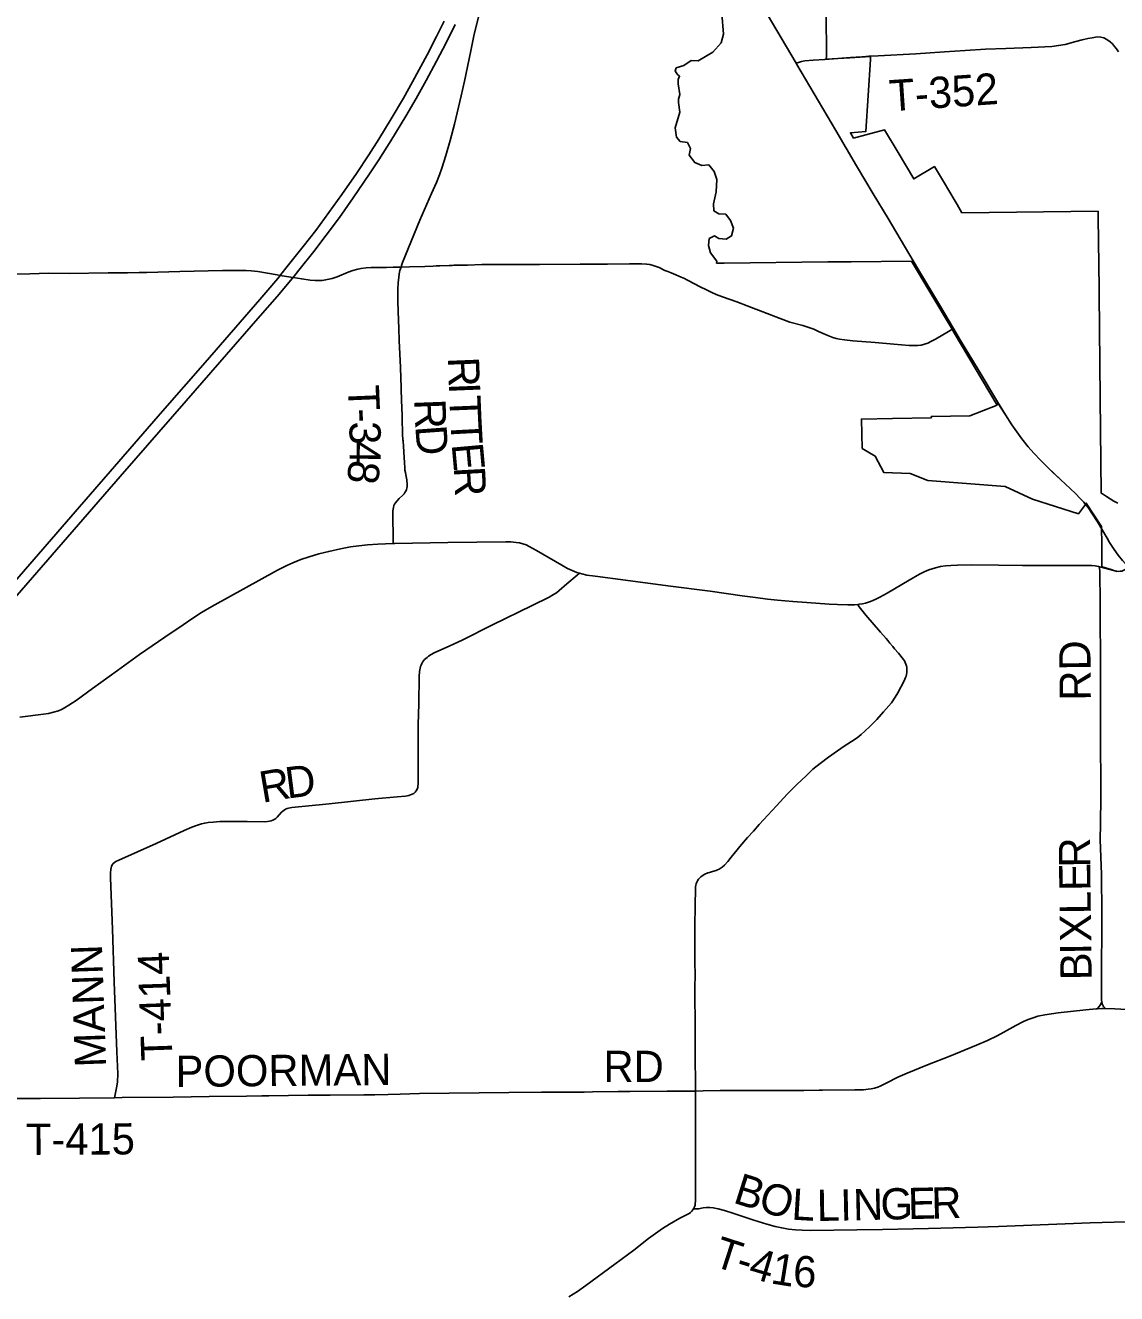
# Model space of a CAD drawing. Extents: x 40529 to 41139, y 15164 to 15584.
# Drawn here: x 40618.2 to 40677.8, y 15358.4 to 15427.7 of the extents above; entities that cross this region are included whole.
import ezdxf

# ---------------------------------------------------------------- set-up
doc = ezdxf.new("R2010")
doc.units = 0
for name, color, linetype in [('GM_X_Corporation', 7, 'Continuous'), ('GM_X_County_Road', 7, 'Continuous'), ('GM_X_Interstate_Route', 7, 'Continuous'), ('GM_X_State_Route', 7, 'Continuous'), ('GM_X_Township_Road', 7, 'Continuous'), ('GM_X_Township_Road_Text', 7, 'Continuous'), ('SH_Data', 7, 'Continuous')]:
    doc.layers.add(name, color=color, linetype=linetype)

msp = doc.modelspace()

# ---------------------------------------------------------------- linework, layer by layer
at = {"layer": 'GM_X_Corporation'}
for points in [[(40677.842, 15397.878), (40677.786, 15397.892), (40677.731, 15397.91), (40677.466, 15398.003), (40677.348, 15398.04), (40677.229, 15398.074), (40677.034, 15398.122), (40677.02, 15398.125), (40677.019, 15398.303), (40677.014, 15399.659), (40677.01, 15399.989), (40677.007, 15400.331), (40676.172, 15401.606), (40676.068, 15401.464), (40675.744, 15401.025), (40673.227, 15401.82), (40671.732, 15402.507), (40667.514, 15402.848), (40666.546, 15403.228), (40665.117, 15403.274), (40664.639, 15404.173), (40663.92, 15404.595), (40663.889, 15406.199), (40665.576, 15406.231), (40667.706, 15406.272), (40667.703, 15406.337), (40669.811, 15406.384), (40671.298, 15406.968), (40668.954, 15410.907), (40668.78, 15411.201), (40666.62, 15414.831), (40663.332, 15414.797), (40662.05, 15414.784), (40656.379, 15414.726), (40655.97, 15414.724), (40655.987, 15414.836), (40655.636, 15415.287), (40655.531, 15415.686), (40655.573, 15416.064), (40655.866, 15416.204), (40656.098, 15416.064), (40656.496, 15416.022), (40656.79, 15416.211), (40656.895, 15416.631), (40656.727, 15417.051), (40656.475, 15417.387), (40656.098, 15417.408), (40655.825, 15417.576), (40655.804, 15417.954), (40655.95, 15418.619), (40655.992, 15419.29), (40655.835, 15419.727), (40655.552, 15420.088), (40655.174, 15420.046), (40654.775, 15420.214), (40654.481, 15420.613), (40654.544, 15420.991), (40654.376, 15421.306), (40653.978, 15421.369), (40653.789, 15421.6), (40653.705, 15422.104), (40653.957, 15422.964), (40653.889, 15423.49), (40653.889, 15423.684), (40653.957, 15423.93), (40653.873, 15424.518), (40653.868, 15424.753), (40653.952, 15424.926), (40653.821, 15425.052), (40653.71, 15425.225), (40653.768, 15425.383), (40654.187, 15425.526), (40654.587, 15425.792), (40654.964, 15425.778), (40655.761, 15426.24), (40656.223, 15426.764), (40656.349, 15427.226), (40656.257, 15428.352)], [(40661.957, 15428.401), (40661.973, 15426.025), (40661.967, 15425.858), (40663.255, 15425.937), (40664.382, 15426.006), (40664.375, 15425.838), (40664.134, 15421.913), (40663.283, 15421.844), (40663.458, 15421.55), (40664.122, 15421.725), (40665.151, 15421.997), (40665.886, 15420.762), (40666.742, 15419.322), (40667.877, 15419.997), (40668.53, 15418.899), (40668.548, 15418.868), (40669.116, 15417.914), (40669.376, 15417.476), (40676.819, 15417.553), (40676.828, 15416.772), (40676.832, 15416.357), (40676.84, 15415.647), (40676.841, 15415.609), (40676.848, 15414.936), (40676.93, 15407.341), (40676.987, 15402.158), (40677.064, 15402.109), (40677.269, 15401.977), (40677.475, 15401.848), (40677.684, 15401.723), (40677.895, 15401.602)]]:
    msp.add_lwpolyline(points, dxfattribs=at)
at = {"layer": 'GM_X_County_Road'}
for points in [[(40617.414, 15414.121), (40618.462, 15414.136), (40619.479, 15414.163), (40620.606, 15414.16), (40622.738, 15414.187), (40623.174, 15414.195), (40623.537, 15414.191), (40623.798, 15414.191), (40624.425, 15414.199), (40624.846, 15414.21), (40626.646, 15414.255), (40628.974, 15414.311), (40629.81, 15414.325), (40630.273, 15414.318), (40630.55, 15414.299), (40630.918, 15414.254), (40631.967, 15414.078), (40632.133, 15414.051), (40632.712, 15413.957), (40632.836, 15413.936), (40633.306, 15413.857), (40633.768, 15413.791), (40634.049, 15413.767), (40634.237, 15413.766), (40634.424, 15413.779), (40634.611, 15413.804), (40634.796, 15413.84), (40634.977, 15413.888), (40635.243, 15413.979), (40635.839, 15414.226), (40636.099, 15414.321), (40636.365, 15414.394), (40636.546, 15414.427), (40636.821, 15414.458), (40637.099, 15414.474), (40637.937, 15414.484), (40638.298, 15414.5), (40638.733, 15414.503)], [(40638.733, 15414.503), (40639.196, 15414.515), (40640.03, 15414.53), (40640.486, 15414.55), (40640.659, 15414.564), (40640.857, 15414.569), (40641.371, 15414.589), (40641.519, 15414.596), (40641.612, 15414.601), (40641.673, 15414.602), (40641.728, 15414.603), (40641.822, 15414.609), (40641.9, 15414.612), (40642.356, 15414.612), (40643.145, 15414.645), (40643.328, 15414.645), (40643.4, 15414.646), (40643.458, 15414.646), (40643.671, 15414.649), (40643.744, 15414.65), (40644.282, 15414.647), (40645.261, 15414.64), (40646.301, 15414.647), (40648.519, 15414.664), (40650.01, 15414.666), (40651.222, 15414.685), (40651.873, 15414.685), (40652.151, 15414.672), (40652.331, 15414.64), (40652.502, 15414.597), (40652.677, 15414.538), (40652.837, 15414.472), (40653.145, 15414.32), (40653.301, 15414.254), (40653.488, 15414.184), (40653.617, 15414.141), (40654.038, 15413.958), (40654.225, 15413.872), (40654.342, 15413.809), (40654.424, 15413.763), (40655.074, 15413.42), (40655.425, 15413.252), (40655.678, 15413.135), (40655.944, 15413.007), (40656.287, 15412.87), (40657.07, 15412.597), (40657.635, 15412.395), (40658.734, 15411.97), (40659.451, 15411.697), (40659.977, 15411.498), (40660.683, 15411.307), (40661.118, 15411.172), (40661.291, 15411.105), (40661.544, 15410.991), (40662.053, 15410.757), (40662.317, 15410.658), (40662.498, 15410.607), (40662.682, 15410.567), (40662.96, 15410.524), (40663.424, 15410.476), (40664.632, 15410.379), (40665.653, 15410.294), (40666.49, 15410.226), (40666.771, 15410.216), (40666.96, 15410.222), (40667.147, 15410.245), (40667.331, 15410.289), (40667.509, 15410.352), (40667.68, 15410.431), (40667.927, 15410.565), (40668.649, 15410.993), (40668.915, 15411.151)], [(40617.91, 15389.921), (40619.206, 15390.077), (40619.48, 15390.121), (40619.751, 15390.183), (40620.015, 15390.266), (40620.185, 15390.337), (40620.351, 15390.418), (40620.59, 15390.56), (40620.976, 15390.818), (40621.883, 15391.472), (40623.24, 15392.46), (40624.452, 15393.328), (40625.827, 15394.288), (40626.824, 15394.964), (40627.364, 15395.331), (40627.829, 15395.633), (40628.404, 15395.957), (40631.989, 15397.949), (40632.489, 15398.199), (40632.83, 15398.352), (40633.264, 15398.52), (40633.705, 15398.671), (40634.243, 15398.828), (40634.785, 15398.967), (40635.423, 15399.109), (40635.974, 15399.213), (40636.436, 15399.282), (40636.9, 15399.33), (40637.459, 15399.368), (40638.3, 15399.401)], [(40638.3, 15399.401), (40638.392, 15399.405), (40641.282, 15399.451), (40644.452, 15399.489), (40644.733, 15399.484), (40645.014, 15399.464), (40645.201, 15399.436), (40645.385, 15399.391), (40645.562, 15399.326), (40645.733, 15399.245), (40646.141, 15399.018), (40647.509, 15398.219), (40647.835, 15398.042), (40648.087, 15397.924), (40648.345, 15397.821), (40648.48, 15397.78)], [(40648.48, 15397.78), (40648.61, 15397.74), (40648.881, 15397.68), (40649.34, 15397.611), (40651.005, 15397.398), (40653.316, 15397.092), (40655.627, 15396.79), (40657.379, 15396.547), (40658.105, 15396.454), (40658.747, 15396.366), (40659.297, 15396.302), (40660.13, 15396.228), (40660.896, 15396.187), (40662.117, 15396.085), (40662.581, 15396.06), (40663.14, 15396.05), (40663.504, 15396.059), (40663.693, 15396.074)], [(40663.693, 15396.074), (40663.757, 15396.079), (40663.938, 15396.104), (40664.117, 15396.146), (40664.38, 15396.232), (40664.636, 15396.34), (40664.886, 15396.462), (40665.292, 15396.688), (40666.497, 15397.399), (40667.066, 15397.721), (40667.317, 15397.847), (40667.575, 15397.959), (40667.752, 15398.024), (40667.932, 15398.078), (40668.207, 15398.138), (40668.485, 15398.18), (40668.765, 15398.208), (40669.139, 15398.225), (40669.886, 15398.228), (40671.377, 15398.223), (40672.682, 15398.206), (40675.293, 15398.202), (40675.754, 15398.203), (40676.209, 15398.204), (40676.477, 15398.197), (40676.661, 15398.178), (40676.846, 15398.143), (40676.892, 15398.131)], [(40676.892, 15398.131), (40677.118, 15398.073), (40677.657, 15397.919), (40677.836, 15397.887), (40677.926, 15397.88), (40678.016, 15397.882), (40678.104, 15397.895), (40678.19, 15397.921), (40678.261, 15397.967), (40678.309, 15398.015), (40678.446, 15398.152)]]:
    msp.add_lwpolyline(points, dxfattribs=at)
at = {"layer": 'GM_X_Interstate_Route'}
for points in [[(40615.607, 15395.019), (40620.689, 15400.855), (40625.703, 15406.623), (40628.029, 15409.295), (40631.027, 15412.741), (40631.993, 15413.878), (40632.133, 15414.051), (40632.169, 15414.095), (40632.517, 15414.532), (40633.391, 15415.624), (40634.075, 15416.51), (40634.796, 15417.485), (40635.501, 15418.471), (40636.294, 15419.623), (40636.966, 15420.632), (40637.517, 15421.497), (40638.196, 15422.612), (40638.859, 15423.736), (40639.363, 15424.63), (40640.16, 15426.107), (40640.677, 15427.099), (40641.09, 15427.934)], [(40617.395, 15396.161), (40623.387, 15403.059), (40627.003, 15407.204), (40631.039, 15411.848), (40631.96, 15412.901), (40632.803, 15413.896), (40632.836, 15413.936), (40633.158, 15414.328), (40633.967, 15415.351), (40634.645, 15416.241), (40635.363, 15417.218), (40636.117, 15418.283), (40637.013, 15419.59), (40637.524, 15420.369), (40638.169, 15421.395), (40638.99, 15422.75), (40639.554, 15423.715), (40640.101, 15424.69), (40640.677, 15425.756), (40641.19, 15426.749), (40641.685, 15427.752)]]:
    msp.add_lwpolyline(points, dxfattribs=at)
at = {"layer": 'GM_X_State_Route'}
for points in [[(40656.221, 15439.212), (40656.386, 15438.467), (40656.534, 15437.735), (40656.695, 15436.815), (40656.88, 15435.617), (40657.181, 15433.493), (40657.36, 15432.294), (40657.515, 15431.186), (40657.608, 15430.635), (40657.676, 15430.366), (40657.764, 15430.103), (40657.872, 15429.848), (40657.996, 15429.6), (40658.224, 15429.194), (40658.734, 15428.328), (40660.317, 15425.637), (40660.353, 15425.577), (40662.489, 15421.965), (40663.621, 15420.034), (40664.526, 15418.511), (40665.341, 15417.151), (40666.718, 15414.843)], [(40666.718, 15414.843), (40667.061, 15414.268), (40668.204, 15412.344), (40668.915, 15411.151), (40669.302, 15410.501), (40670.263, 15408.902), (40671.311, 15407.139), (40671.364, 15407.053)], [(40671.364, 15407.053), (40671.75, 15406.423), (40672.104, 15405.877), (40672.37, 15405.495), (40672.65, 15405.123), (40673.001, 15404.689), (40673.306, 15404.338), (40673.687, 15403.929), (40674.083, 15403.534), (40674.323, 15403.307)], [(40674.323, 15403.307), (40674.76, 15402.894), (40675.58, 15402.132), (40675.844, 15401.866), (40676.033, 15401.658), (40676.056, 15401.628)], [(40676.056, 15401.628), (40676.265, 15401.364), (40676.477, 15401.055), (40676.775, 15400.581), (40677.306, 15399.697)], [(40677.306, 15399.697), (40677.447, 15399.461), (40677.701, 15399.071), (40677.917, 15398.769), (40678.148, 15398.478), (40678.332, 15398.269), (40678.446, 15398.152)]]:
    msp.add_lwpolyline(points, dxfattribs=at)
at = {"layer": 'GM_X_Township_Road'}
for points in [[(40638.733, 15414.503), (40638.76, 15414.585), (40638.822, 15414.756), (40639.76, 15417.075), (40640.392, 15418.527), (40640.663, 15419.123), (40640.837, 15419.552), (40640.959, 15419.901), (40641.183, 15420.608), (40641.415, 15421.412), (40641.651, 15422.312), (40642.021, 15423.852), (40642.207, 15424.669), (40642.549, 15426.31), (40642.734, 15427.224), (40642.885, 15427.86), (40642.99, 15428.241), (40642.998, 15428.268)], [(40664.293, 15426.02), (40664.806, 15426.054), (40666.853, 15426.158), (40668.429, 15426.263), (40669.554, 15426.337), (40670.658, 15426.41), (40671.775, 15426.454), (40673.167, 15426.501), (40674.294, 15426.55), (40675.015, 15426.668), (40675.592, 15426.831), (40675.952, 15426.915), (40676.248, 15426.989), (40676.499, 15427.032), (40676.766, 15427.082), (40676.963, 15427.072), (40677.131, 15427.033), (40677.299, 15426.939), (40677.476, 15426.811), (40677.6, 15426.702), (40677.713, 15426.559), (40677.817, 15426.421), (40677.93, 15426.263)], [(40661.884, 15425.854), (40663.291, 15425.948), (40663.901, 15425.994), (40663.97, 15425.999), (40664.293, 15426.02)], [(40660.317, 15425.637), (40660.511, 15425.704), (40660.603, 15425.736), (40660.789, 15425.767), (40661.252, 15425.812), (40661.884, 15425.854)], [(40638.558, 15412.636), (40638.553, 15412.823), (40638.559, 15413.289), (40638.583, 15413.662), (40638.611, 15413.941), (40638.637, 15414.128), (40638.676, 15414.312), (40638.733, 15414.503)], [(40638.84, 15405.074), (40638.82, 15405.38), (40638.81, 15405.667), (40638.8, 15405.95), (40638.789, 15406.32), (40638.778, 15406.878), (40638.766, 15407.156), (40638.748, 15407.898), (40638.695, 15409.009), (40638.627, 15410.497), (40638.616, 15411.143), (40638.573, 15412.074), (40638.558, 15412.636)], [(40638.3, 15399.401), (40638.298, 15399.597), (40638.282, 15400.996), (40638.281, 15401.178), (40638.295, 15401.286), (40638.318, 15401.377), (40638.348, 15401.471), (40638.382, 15401.545), (40638.433, 15401.629), (40638.504, 15401.714), (40638.632, 15401.855), (40638.836, 15402.044), (40638.896, 15402.113), (40638.948, 15402.187), (40638.994, 15402.264), (40639.029, 15402.346), (40639.054, 15402.432), (40639.069, 15402.521), (40639.074, 15402.608), (40639.054, 15402.884), (40638.999, 15403.153), (40638.968, 15403.281), (40638.948, 15403.412), (40638.932, 15403.547), (40638.915, 15403.813), (40638.844, 15405.013), (40638.84, 15405.074)], [(40623.087, 15369.122), (40623.215, 15369.754), (40623.247, 15369.997), (40623.253, 15370.425), (40623.21, 15371.635), (40623.061, 15375.45), (40622.963, 15378.335), (40622.856, 15381.127), (40622.86, 15381.406), (40622.877, 15381.589), (40622.895, 15381.677), (40622.921, 15381.761), (40622.957, 15381.84), (40623.01, 15381.91), (40623.076, 15381.97), (40623.149, 15382.021), (40623.311, 15382.109), (40624.333, 15382.556), (40625.356, 15383.009), (40626.876, 15383.716), (40627.302, 15383.902), (40627.562, 15384), (40627.827, 15384.081), (40628.006, 15384.123), (40628.188, 15384.153), (40628.464, 15384.182), (40628.835, 15384.205), (40629.3, 15384.216), (40630.324, 15384.207), (40631.256, 15384.203), (40631.445, 15384.212), (40631.54, 15384.224), (40631.633, 15384.246), (40631.724, 15384.278), (40631.81, 15384.322), (40631.889, 15384.378), (40631.96, 15384.442), (40632.209, 15384.721), (40632.274, 15384.784), (40632.343, 15384.84), (40632.42, 15384.885), (40632.503, 15384.919), (40632.589, 15384.946), (40632.769, 15384.979), (40633.14, 15385.011), (40633.51, 15385.047), (40634.808, 15385.18), (40637.308, 15385.448), (40638.514, 15385.559), (40638.98, 15385.604), (40639.167, 15385.638), (40639.258, 15385.664), (40639.347, 15385.701), (40639.43, 15385.751), (40639.504, 15385.814), (40639.565, 15385.891), (40639.612, 15385.977), (40639.643, 15386.069), (40639.658, 15386.164), (40639.667, 15386.259), (40639.669, 15387.006), (40639.668, 15388.496), (40639.677, 15389.52), (40639.71, 15390.637), (40639.732, 15392.128), (40639.744, 15392.405), (40639.772, 15392.585), (40639.795, 15392.673), (40639.825, 15392.758), (40639.862, 15392.839), (40639.908, 15392.917), (40639.96, 15392.991), (40640.018, 15393.06), (40640.083, 15393.123), (40640.153, 15393.182), (40640.226, 15393.237), (40640.382, 15393.334), (40640.546, 15393.419), (40641.393, 15393.806), (40642.066, 15394.127), (40643.736, 15394.955), (40645.9, 15396.021), (40646.82, 15396.475), (40647.066, 15396.611), (40647.225, 15396.711), (40647.375, 15396.825), (40647.798, 15397.191), (40648.358, 15397.674), (40648.48, 15397.78)], [(40677.012, 15374.369), (40677.008, 15374.454), (40677.006, 15374.535), (40677.001, 15374.727), (40676.993, 15374.982), (40677.003, 15375.377), (40677.021, 15379.167), (40676.994, 15381.308), (40676.928, 15383.236), (40676.944, 15384.078), (40676.974, 15385.563), (40676.963, 15386.484), (40676.953, 15388.303), (40676.938, 15391.195), (40676.938, 15392.93), (40676.928, 15395.48), (40676.931, 15396.506), (40676.912, 15397.53), (40676.903, 15397.809), (40676.892, 15398.131)], [(40654.821, 15369.482), (40654.819, 15370.052), (40654.808, 15371.17), (40654.804, 15371.634), (40654.799, 15372.84), (40654.789, 15375.066), (40654.796, 15375.903), (40654.792, 15376.46), (40654.789, 15377.483), (40654.788, 15378.412), (40654.801, 15379.711), (40654.812, 15380.454), (40654.825, 15380.637), (40654.839, 15380.726), (40654.861, 15380.813), (40654.893, 15380.897), (40654.933, 15380.978), (40654.981, 15381.053), (40655.038, 15381.121), (40655.103, 15381.182), (40655.176, 15381.236), (40655.334, 15381.327), (40655.497, 15381.4), (40655.581, 15381.429), (40655.758, 15381.48), (40655.941, 15381.532), (40656.029, 15381.569), (40656.111, 15381.61), (40656.269, 15381.719), (40656.399, 15381.825), (40656.585, 15382.035), (40656.775, 15382.268), (40656.929, 15382.458), (40657.091, 15382.656), (40657.245, 15382.849), (40657.668, 15383.344), (40657.981, 15383.691), (40658.305, 15384.051), (40659.242, 15385.075), (40659.823, 15385.708), (40660.357, 15386.241), (40660.859, 15386.716), (40661.238, 15387.068), (40661.626, 15387.38), (40662.08, 15387.736), (40662.581, 15388.072), (40662.95, 15388.333), (40663.351, 15388.576), (40663.657, 15388.789), (40663.874, 15388.961), (40664.079, 15389.141), (40664.344, 15389.398), (40664.729, 15389.794), (40665.096, 15390.209), (40665.52, 15390.689), (40665.728, 15390.998), (40665.871, 15391.239), (40666.212, 15391.901), (40666.29, 15392.072), (40666.322, 15392.161), (40666.348, 15392.253), (40666.365, 15392.347), (40666.374, 15392.442), (40666.373, 15392.537), (40666.364, 15392.632), (40666.346, 15392.724), (40666.319, 15392.815), (40666.282, 15392.904), (40666.237, 15392.988), (40666.186, 15393.068), (40665.911, 15393.417), (40665.701, 15393.65), (40665.603, 15393.769), (40665.44, 15393.954), (40665.322, 15394.108), (40665.244, 15394.206), (40664.931, 15394.559), (40664.124, 15395.48), (40663.826, 15395.842), (40663.77, 15395.94), (40663.693, 15396.074)], [(40677.214, 15373.991), (40677.738, 15373.977), (40678.393, 15373.934), (40680.151, 15373.779), (40681.636, 15373.717), (40682.675, 15373.651), (40683.787, 15373.568), (40684.429, 15373.513), (40684.623, 15373.506), (40684.716, 15373.503), (40684.802, 15373.506), (40684.895, 15373.52), (40684.989, 15373.554), (40685.061, 15373.603), (40685.141, 15373.662), (40685.207, 15373.724), (40685.273, 15373.785), (40685.394, 15373.922), (40685.619, 15374.218), (40686.752, 15375.814), (40687.777, 15377.281)], [(40676.791, 15373.986), (40676.862, 15374.083), (40676.945, 15374.194), (40676.972, 15374.253), (40677.012, 15374.369)], [(40677.214, 15373.991), (40677.111, 15374.112), (40677.062, 15374.211), (40677.012, 15374.369)], [(40654.821, 15369.482), (40655.236, 15369.489), (40656.169, 15369.508), (40660.742, 15369.518), (40661.581, 15369.525), (40661.766, 15369.535), (40663.532, 15369.547), (40663.993, 15369.561), (40664.254, 15369.584), (40664.42, 15369.609), (40664.595, 15369.65), (40664.774, 15369.706), (40664.939, 15369.77), (40665.267, 15369.926), (40665.88, 15370.238), (40666.378, 15370.464), (40667.501, 15370.924), (40668.715, 15371.398), (40670.181, 15371.989), (40670.773, 15372.245), (40671.293, 15372.496), (40671.673, 15372.699), (40672.33, 15373.067), (40672.746, 15373.281), (40673.004, 15373.392), (40673.265, 15373.491), (40673.532, 15373.572), (40673.899, 15373.645), (40674.635, 15373.75), (40676.154, 15373.927), (40676.717, 15373.984), (40676.791, 15373.986)], [(40676.791, 15373.986), (40677.022, 15373.992), (40677.214, 15373.991)], [(40623.087, 15369.122), (40623.501, 15369.129), (40626.292, 15369.155), (40628.247, 15369.185), (40630.298, 15369.211), (40631.137, 15369.217), (40631.511, 15369.217), (40633.655, 15369.259), (40634.86, 15369.267), (40636.707, 15369.271), (40637.302, 15369.281), (40638.022, 15369.295), (40638.685, 15369.322), (40639.736, 15369.353), (40644.63, 15369.401), (40646.402, 15369.418), (40647.8, 15369.42), (40648.731, 15369.431), (40649.197, 15369.434), (40650.591, 15369.462), (40651.241, 15369.465), (40653.28, 15369.471), (40653.995, 15369.478), (40654.821, 15369.482)], [(40654.715, 15363.05), (40654.73, 15363.078), (40654.767, 15363.167), (40654.794, 15363.259), (40654.81, 15363.353), (40654.818, 15363.446), (40654.828, 15363.819), (40654.824, 15367.538), (40654.821, 15369.482)], [(40615.981, 15368.667), (40616.025, 15368.772), (40616.084, 15368.851), (40616.155, 15368.92), (40616.234, 15368.974), (40616.327, 15369.012), (40616.419, 15369.044), (40616.513, 15369.063), (40616.702, 15369.079), (40619.033, 15369.084), (40621.174, 15369.099), (40623.087, 15369.122)], [(40647.9, 15358.236), (40648.367, 15358.541), (40648.825, 15358.863), (40650.405, 15360.02), (40651.457, 15360.793), (40652.261, 15361.425), (40652.63, 15361.707), (40653.012, 15361.97), (40653.405, 15362.217), (40653.97, 15362.541), (40654.468, 15362.8), (40654.548, 15362.853), (40654.621, 15362.916), (40654.683, 15362.993), (40654.715, 15363.05)], [(40654.715, 15363.05), (40654.836, 15363.053), (40654.999, 15363.057), (40655.151, 15363.092), (40655.24, 15363.108), (40655.422, 15363.127), (40655.604, 15363.127), (40655.786, 15363.108), (40656.056, 15363.053), (40656.413, 15362.955), (40656.855, 15362.812), (40658.004, 15362.427), (40658.718, 15362.209), (40659.17, 15362.089), (40659.536, 15362.009), (40659.905, 15361.948), (40660.277, 15361.904), (40660.65, 15361.88), (40661.118, 15361.873), (40663.636, 15361.899), (40665.034, 15361.926), (40667.55, 15361.967), (40670.251, 15362.042), (40671.368, 15362.09), (40676.389, 15362.279), (40678.998, 15362.363)]]:
    msp.add_lwpolyline(points, dxfattribs=at)
at = {"layer": 'SH_Data'}
msp.add_lwpolyline([(40658.734, 15428.328), (40660.317, 15425.637), (40660.353, 15425.577), (40662.489, 15421.965), (40663.621, 15420.034), (40664.526, 15418.511), (40665.341, 15417.151), (40666.718, 15414.843), (40667.061, 15414.268), (40668.204, 15412.344), (40668.915, 15411.151), (40669.302, 15410.501), (40670.263, 15408.902), (40671.311, 15407.139), (40671.75, 15406.423), (40672.104, 15405.877), (40672.37, 15405.495), (40672.65, 15405.123), (40673.001, 15404.689), (40673.306, 15404.338), (40673.687, 15403.929), (40674.083, 15403.534), (40674.76, 15402.894), (40675.58, 15402.132), (40675.844, 15401.866), (40676.033, 15401.658), (40676.265, 15401.364), (40676.477, 15401.055), (40676.775, 15400.581), (40677.306, 15399.697), (40677.447, 15399.461), (40677.701, 15399.071), (40677.917, 15398.769)], dxfattribs=at)

# ---------------------------------------------------------------- texts
at = {"layer": 'GM_X_Township_Road_Text'}
for s, height, rotation, p in [('T-352', 1.7063, 3.92577, (40665.466, 15423.011)), ('R', 1.706, 272.31901, (40641.284, 15409.567)), ('T', 1.706, 272.37061, (40635.822, 15408.022)), ('I', 1.706, 272.31901, (40641.34, 15408.167)), ('T', 1.706, 272.31922, (40641.369, 15407.467)), ('-', 1.706, 272.20951, (40635.874, 15406.749)), ('R', 1.706, 272.1627, (40639.454, 15407.272)), ('3', 1.706, 271.53537, (40635.901, 15406.054)), ('T', 1.706, 273.07903, (40641.422, 15406.167)), ('D', 1.706, 274.14346, (40639.51, 15405.808)), ('4', 1.706, 269.36507, (40635.929, 15405.02)), ('E', 1.706, 275.17215, (40641.495, 15404.826)), ('8', 1.706, 262.90466, (40635.921, 15404.02)), ('R', 1.706, 273.10039, (40641.609, 15403.571)), ('RD', 1.7063, 90.48898, (40676.421, 15390.821)), ('D', 1.706, 7.32383, (40632.518, 15385.462)), ('R', 1.706, 9.67471, (40631.155, 15385.229)), ('R', 1.706, 90.22638, (40676.387, 15381.698)), ('E', 1.706, 90.77573, (40676.404, 15380.426)), ('L', 1.706, 90.78002, (40676.422, 15379.15)), ('X', 1.706, 90.77794, (40676.442, 15377.649)), ('MANN', 1.7063, 91.99712, (40622.626, 15370.809)), ('T-414', 1.7063, 91.96526, (40626.251, 15371.163)), ('I', 1.706, 90.7728, (40676.452, 15376.948)), ('B', 1.706, 90.78064, (40676.471, 15375.547)), ('POORMAN', 1.7063, 0.54322, (40626.423, 15369.706)), ('RD', 1.7063, 0.00001, (40649.793, 15369.98)), ('T-415', 1.7063, 0.28122, (40618.238, 15365.997)), ('B', 1.706, 342.45249, (40656.816, 15363.402)), ('O', 1.706, 343.33476, (40658.179, 15362.971)), ('L', 1.706, 356.49178, (40660.038, 15362.465)), ('L', 1.706, 0.98582, (40661.458, 15362.384)), ('I', 1.706, 1.22966, (40662.742, 15362.406)), ('N', 1.706, 1.23559, (40663.443, 15362.421)), ('G', 1.706, 1.23317, (40664.944, 15362.453)), ('E', 1.706, 1.23481, (40666.445, 15362.486)), ('R', 1.706, 1.2334, (40667.721, 15362.513)), ('T', 1.706, 342.04954, (40655.705, 15359.948)), ('-', 1.706, 342.76017, (40656.941, 15359.547)), ('4', 1.706, 343.66308, (40657.638, 15359.331)), ('1', 1.706, 350.9297, (40658.877, 15358.984)), ('6', 1.706, 357.47128, (40660.126, 15358.797))]:
    msp.add_text(s, height=height, rotation=rotation, dxfattribs=at).set_placement(p)

doc.saveas('drawing.dxf')
